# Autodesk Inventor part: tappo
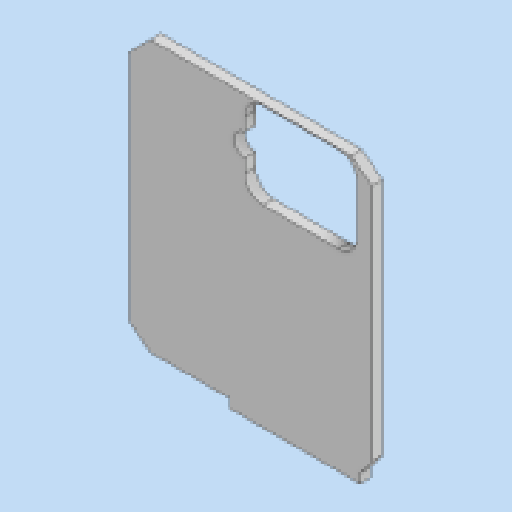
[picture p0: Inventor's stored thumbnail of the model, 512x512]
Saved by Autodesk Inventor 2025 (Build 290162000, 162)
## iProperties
Created: 2025-03
Part Number: tappo
Material: Generico
Document SubType Name: Modeling
Designer: Ryzen5700u
Density: 1 g/cm^3
Appearance: Default
Author: Ryzen5700u
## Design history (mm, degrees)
sketch "Schizzo1"
  geometry: L1 (-13.5, -12.599)-(15.5, -12.599) reference; L2 (15.5, -12.599)-(15.5, -10.099) reference; L3 (15.5, -10.099)-(-7, -10.099) reference; L4 (-7, -10.099)-(-13, -5.599) reference; L5 (-13, -5.599)-(-13, 60.901) reference; L6 (-13, 60.901)-(-7, 66.901) reference; L7 (-7, 66.901)-(50, 66.901) reference; L8 (50, 66.901)-(56, 62.401) reference; L9 (56, 62.401)-(56, -5.432) reference; L10 (56, -5.432)-(52.5, -10.099) reference; L11 (52.5, -10.099)-(52.5, -12.599) reference; L12 (52.5, -12.599)-(56.5, -12.599) reference; L13 (58.5, -10.599)-(58.5, 67.401) reference; L14 (56.5, 69.401)-(-13.5, 69.401) reference; L15 (-15.5, 67.401)-(-15.5, -10.599) reference; L16 (52.5, -12.599)-(15.5, -12.599); L17 (51.5, 47.401)-(51.5, 61.401) reference; L18 (46.5, 66.401)-(25, 66.401) reference; L19 (25, 42.401)-(46.5, 42.401) reference; L20 (20, 61.401)-(20, 47.401) reference; L21 (51.7, 61.401)-(51.7, 47.401); L22 (46.5, 42.201)-(25, 42.201); L23 (19.8, 47.401)-(19.8, 61.401); L24 (25, 66.601)-(46.5, 66.601); C1 r 1 at (-12.5, 66.401) reference; C2 r 1 at (55.5, 66.401) reference; C3 r 1 at (55.5, -9.599) reference; C4 r 1 at (-12.5, -9.599) reference; C5 r 3.23 at (20, 54.401); A1 r 2 centre (-13.5, -10.599) between (-15.5, -10.599) and (-13.5, -12.599) reference; A2 r 2 centre (56.5, -10.599) between (56.5, -12.599) and (58.5, -10.599) reference; A3 r 2 centre (56.5, 67.401) between (58.5, 67.401) and (56.5, 69.401) reference; A4 r 2 centre (-13.5, 67.401) between (-13.5, 69.401) and (-15.5, 67.401) reference; A5 r 5 centre (46.5, 61.401) between (51.5, 61.401) and (46.5, 66.401) reference; A6 r 5 centre (46.5, 47.401) between (46.5, 42.401) and (51.5, 47.401) reference; A7 r 5 centre (25, 47.401) between (20, 47.401) and (25, 42.401) reference; A8 r 5 centre (25, 61.401) between (25, 66.401) and (20, 61.401) reference; A9 r 5.2 centre (46.5, 47.401) between (46.5, 42.201) and (51.7, 47.401); A10 r 5.2 centre (25, 47.401) between (19.8, 47.401) and (25, 42.201); A11 r 5.2 centre (25, 61.401) between (25, 66.601) and (19.8, 61.401); A12 r 5.2 centre (46.5, 61.401) between (51.7, 61.401) and (46.5, 66.601); 5 further points
  constraints: 10 end point, 8 point on circle, 5 centre point, 1 horizontal, 1 midpoint, 7 other
  dimensions: "d7" = 0.2 distance between parallel lines of L17 L21
extrude "Estrusione1" new body sketch "Schizzo1" distance "d0" = 3; taper "d1" = 0 deg
sketch "Schizzo2"
  geometry: L1 (58.5, -10.599)-(58.5, 67.401) reference; L2 (56.5, 69.401)-(-13.5, 69.401) reference; L3 (-15.5, 67.401)-(-15.5, -10.599) reference; L4 (-13.5, -12.599)-(56.5, -12.599) reference; L5 (50.5, 47.401)-(50.5, 61.401); L6 (46.5, 65.401)-(25, 65.401); L7 (21, 61.401)-(21, 56.395); L8 (21, 52.408)-(21, 47.401); L9 (25, 43.401)-(46.5, 43.401); A1 r 2 centre (56.5, -10.599) between (56.5, -12.599) and (58.5, -10.599) reference; A2 r 2 centre (56.5, 67.401) between (58.5, 67.401) and (56.5, 69.401) reference; A3 r 2 centre (-13.5, 67.401) between (-13.5, 69.401) and (-15.5, 67.401) reference; A4 r 2 centre (-13.5, -10.599) between (-15.5, -10.599) and (-13.5, -12.599) reference; A5 r 4 centre (46.5, 61.401) between (50.5, 61.401) and (46.5, 65.401); A6 r 4 centre (25, 61.401) between (25, 65.401) and (21, 61.401); A7 r 2.23 centre (20, 54.401) between (21, 56.395) and (21, 52.408); A8 r 4 centre (25, 47.401) between (21, 47.401) and (25, 43.401); A9 r 4 centre (46.5, 47.401) between (46.5, 43.401) and (50.5, 47.401); 1 further point
  constraints: 10 end point, 10 point on circle, 5 centre point
extrude "Estrusione2" join sketch "Schizzo2" distance "d3" = 7.5; taper "d4" = 0 deg
node "Solido1"
node "Riferimento1"
node "Riferimento2"
node "Riferimento3"
node "Riferimento4"
node "Riferimento5"
node "Riferimento6"
node "Riferimento7"
node "Riferimento8"
node "Riferimento9"
node "Linea chiusa proiettata1"
feature "ʳ耀ʴ耀ʵ耀ʶ耀ʷ耀ʸ耀ʹ耀ʺ耀"
feature "˗耀˘耀˙耀˚耀˛耀˜耀˝耀˞耀"
